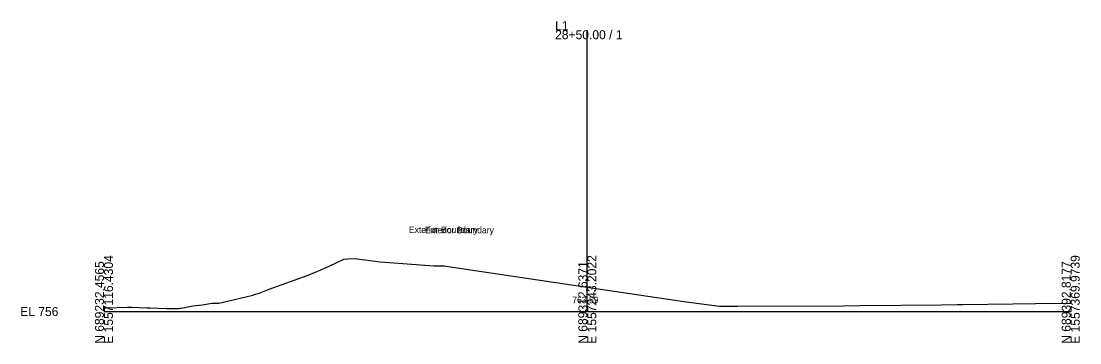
# Model space of a CAD drawing. Extents: x -26 to 2603, y -3010 to 9589.
# Drawn here: x 974.3 to 1302.8, y 1990.3 to 2090 of the extents above; entities that cross this region are included whole.
import ezdxf

# ---------------------------------------------------------------- set-up
doc = ezdxf.new("R2010")
doc.units = 0
for name, color, linetype in [('Default', 7, 'Continuous'), ('Exist Cross Section Cell', 7, 'Continuous'), ('Exist XS Center Line Elevation Label', 7, 'Continuous'), ('Exist XS Ground Line', 7, 'Continuous')]:
    doc.layers.add(name, color=color, linetype=linetype)

msp = doc.modelspace()

# ---------------------------------------------------------------- linework, layer by layer
at = {"layer": 'Exist Cross Section Cell'}
for p, q in [((1150, 2000), (1150, 2087.24)), ((1000, 2000), (1150, 2000)), ((1150, 2000), (1300, 2000))]:
    msp.add_line(p, q, dxfattribs=at)
at = {"layer": 'Exist XS Ground Line'}
msp.add_lwpolyline([(1000, 2001.13), (1000.76, 2001.15), (1007.32, 2001.38), (1007.72, 2001.37), (1008.69, 2001.34), (1013.34, 2001.2), (1014.26, 2001.16), (1019.39, 2000.99), (1023.3, 2000.98), (1023.61, 2001), (1023.95, 2001.06), (1027.6, 2001.77), (1030.46, 2002.13), (1033.57, 2002.56), (1035.65, 2002.59), (1036.53, 2002.77), (1046.23, 2005.13), (1046.89, 2005.35), (1048.14, 2005.73), (1051.31, 2006.92), (1063.4, 2011.26), (1067.33, 2012.98), (1069.92, 2014.11), (1074.47, 2016.21), (1075.69, 2016.32), (1077.77, 2016.44), (1085.69, 2015.46), (1087.12, 2015.29), (1089.99, 2015.12), (1102.41, 2014.18), (1105.6, 2014.18), (1107.5, 2013.91), (1150, 2007.58), (1179.93, 2003.12), (1191.06, 2001.69), (1191.56, 2001.63), (1194.15, 2001.64), (1194.96, 2001.65), (1196.62, 2001.66), (1229.35, 2001.78), (1234.63, 2001.87), (1259.76, 2002.1), (1264.8, 2002.16), (1266.43, 2002.18), (1282.01, 2002.39), (1289.08, 2002.49), (1300, 2002.61)], dxfattribs=at)

# ---------------------------------------------------------------- texts
at = {"layer": 'Default'}
for s, height, p in [('Exterior Boundary', 2, (1094.61, 2024.37)), ('Exterior Boundary', 2, (1099.61, 2024.27)), ('-', 0.0001, (1000, 2000))]:
    msp.add_text(s, height=height, dxfattribs=at).set_placement(p)
at = {"layer": 'Exist Cross Section Cell'}
for s, p in [('L1', (1140, 2087.24)), ('28+50.00 / 1', (1140, 2084.44)), ('EL 756', (974, 1998.6))]:
    msp.add_text(s, height=2.8, dxfattribs=at).set_placement(p)
for s, p in [('E 1557116.4304', (1002.8, 1990)), ('E 1557243.2022', (1152.8, 1990)), ('E 1557369.9739', (1302.8, 1990)), ('N 689232.4565', (1000, 1990)), ('N 689312.6371', (1150, 1990)), ('N 689392.8177', (1300, 1990))]:
    msp.add_text(s, height=2.8, rotation=90, dxfattribs=at).set_placement(p)
at = {"layer": 'Exist XS Center Line Elevation Label'}
msp.add_text('763.59', height=2, dxfattribs=at).set_placement((1145.31, 2002.59))

doc.saveas('drawing.dxf')
